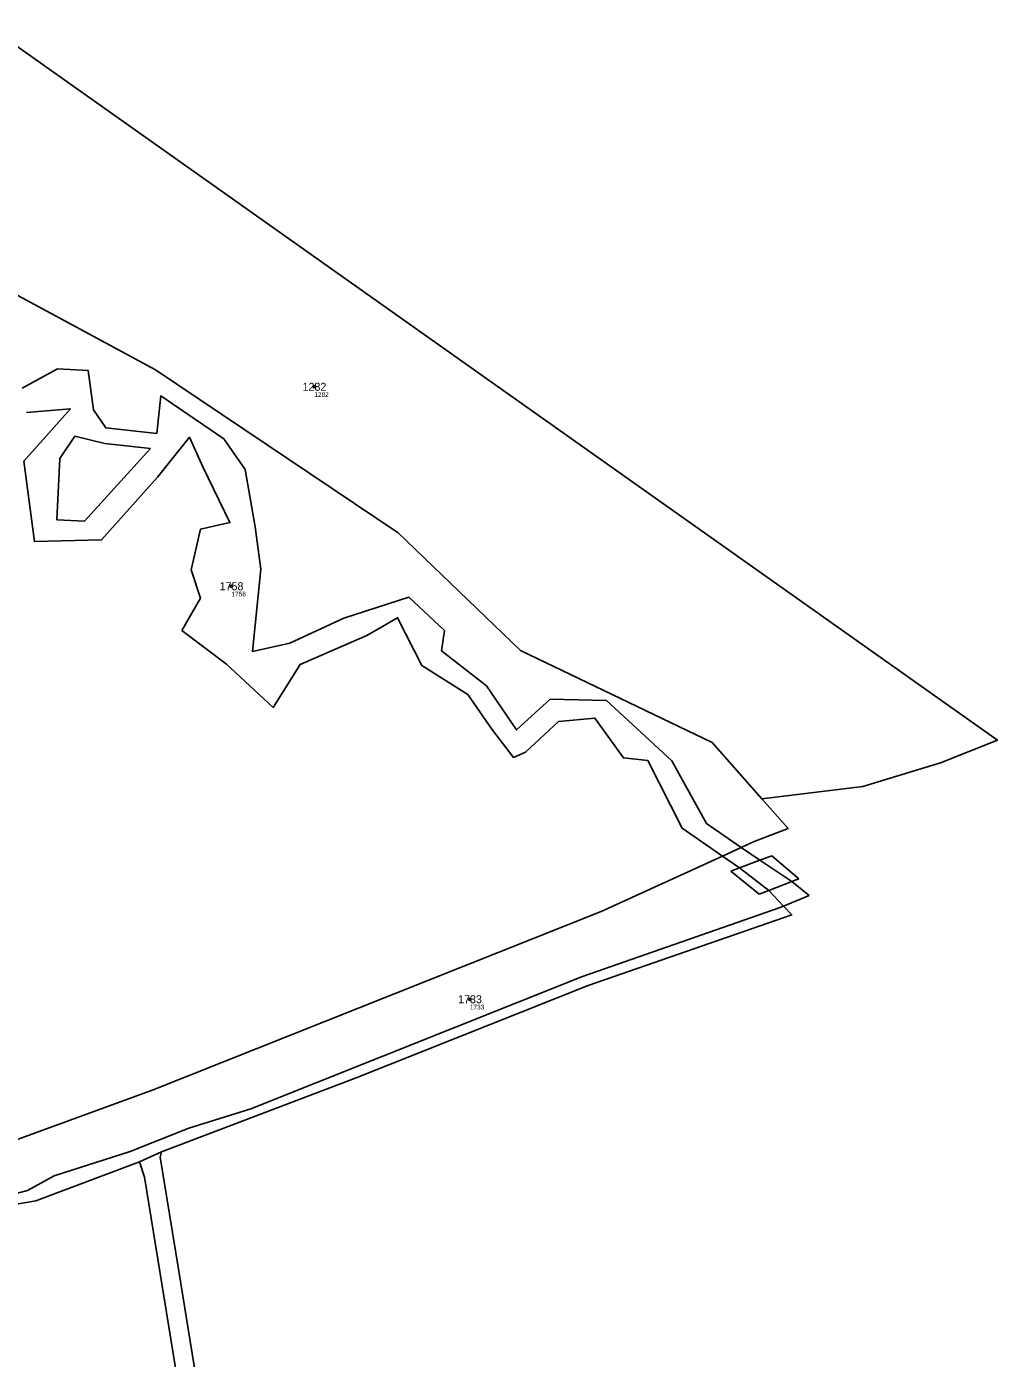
# Model space of a CAD drawing. Extents: x -781091 to -780384, y -1093010 to -1092030.
# Drawn here: x -780590.6 to -780384.4, y -1092590.4 to -1092307.5 of the extents above; entities that cross this region are included whole.
import ezdxf

# ---------------------------------------------------------------- set-up
doc = ezdxf.new("R2010")
doc.units = 0
for name, color, linetype in [('Vrstva 1', 7, 'Continuous'), ('Vrstva 2', 7, 'Continuous'), ('Vrstva 4', 7, 'Continuous'), ('Vrstva 50', 7, 'Continuous'), ('Vrstva 51', 7, 'Continuous')]:
    doc.layers.add(name, color=color, linetype=linetype)

msp = doc.modelspace()

# ---------------------------------------------------------------- linework, layer by layer
at = {"layer": 'Vrstva 1'}
for p, q in [((-780428.87, -1092477.84), (-780434.43, -1092471.52)), ((-780428.07, -1092496.18), (-780471.31, -1092511.15)), ((-780566.65, -1092548.58), (-780562, -1092546.47)), ((-780558.33, -1092571.84), (-780541.89, -1092672.78))]:
    msp.add_line(p, q, dxfattribs=at)
for points in [[(-780384.4, -1092459.05), (-780494.05, -1092381.46), (-780616.5, -1092294.82)], [(-780434.43, -1092471.52), (-780444.96, -1092459.56), (-780485.72, -1092440), (-780511.7, -1092415.04), (-780563.24, -1092380.4), (-780628.93, -1092345.03), (-780635.51, -1092325.46), (-780626.4, -1092311.9)], [(-780591.62, -1092384.31), (-780584.09, -1092380.2), (-780577.59, -1092380.54), (-780576.43, -1092388.86), (-780573.82, -1092392.75), (-780563, -1092393.9), (-780562.1, -1092385.91), (-780548.77, -1092395.06), (-780544.19, -1092401.58), (-780542.06, -1092413.74), (-780540.85, -1092422.73), (-780542.68, -1092440.2), (-780534.7, -1092438.42), (-780523.28, -1092433.14), (-780509.41, -1092428.65), (-780501.89, -1092435.79), (-780502.48, -1092440.08), (-780492.92, -1092447.52), (-780486.58, -1092456.87), (-780479.41, -1092450.33), (-780467.46, -1092450.64), (-780453.55, -1092463.43), (-780446.2, -1092476.76), (-780438.83, -1092481.84)], [(-780442.83, -1092483.67), (-780451.37, -1092477.74), (-780458.67, -1092463.36), (-780463.84, -1092462.82), (-780469.92, -1092454.36), (-780477.64, -1092455.07), (-780484.65, -1092461.6), (-780487.21, -1092462.7), (-780491.81, -1092456.74), (-780496.87, -1092449.32), (-780506.68, -1092443.21), (-780511.84, -1092433.06), (-780518.39, -1092436.81), (-780532.51, -1092442.95), (-780538.26, -1092452.08), (-780548.16, -1092442.92), (-780557.65, -1092435.73), (-780553.71, -1092428.88), (-780555.7, -1092422.88), (-780553.69, -1092414.22), (-780547.46, -1092412.85), (-780553.22, -1092400.98), (-780556.07, -1092394.72), (-780562.85, -1092403.17), (-780574.71, -1092416.51), (-780589, -1092416.87), (-780591.25, -1092399.82), (-780581.34, -1092388.68), (-780590.69, -1092389.44)], [(-780434.43, -1092471.52), (-780412.99, -1092468.92), (-780396.51, -1092463.88), (-780384.4, -1092459.05)], [(-780438.83, -1092481.84), (-780436.05, -1092480.57), (-780428.87, -1092477.84)], [(-780438.83, -1092481.84), (-780434.87, -1092484.57), (-780428.04, -1092489.08), (-780424.36, -1092492.02)], [(-780599.09, -1092546.21), (-780563.77, -1092533.33), (-780468.56, -1092495.42), (-780442.83, -1092483.67)], [(-780428.07, -1092496.18), (-780429.83, -1092494.3), (-780432.93, -1092490.97), (-780439.21, -1092486.18), (-780442.83, -1092483.67)], [(-780471.31, -1092511.15), (-780520.62, -1092530.74), (-780562, -1092546.47)], [(-780562, -1092546.47), (-780562.27, -1092547.65), (-780558.33, -1092571.84)], [(-780566.65, -1092548.58), (-780588.7, -1092556.87), (-780619.47, -1092562.21), (-780643.35, -1092566.12)], [(-780542.57, -1092690.03), (-780545.84, -1092673.37), (-780565.63, -1092551.86), (-780566.65, -1092548.58)]]:
    msp.add_lwpolyline(points, dxfattribs=at)
at = {"layer": 'Vrstva 4'}
for p, q in [((-780580.4, -1092394.52), (-780583.61, -1092399.24)), ((-780574.04, -1092396.04), (-780580.4, -1092394.52)), ((-780578.34, -1092412.57), (-780564.34, -1092397.11)), ((-780564.34, -1092397.11), (-780574.04, -1092396.04)), ((-780583.61, -1092399.24), (-780584.2, -1092412.26)), ((-780584.2, -1092412.26), (-780578.34, -1092412.57)), ((-780442.83, -1092483.67), (-780438.83, -1092481.84)), ((-780439.21, -1092486.18), (-780441.05, -1092486.86)), ((-780434.87, -1092484.57), (-780439.21, -1092486.18)), ((-780432.3, -1092483.62), (-780434.87, -1092484.57)), ((-780426.58, -1092488.51), (-780432.3, -1092483.62)), ((-780441.05, -1092486.86), (-780434.98, -1092491.76)), ((-780428.04, -1092489.08), (-780426.58, -1092488.51)), ((-780434.98, -1092491.76), (-780432.93, -1092490.97)), ((-780432.93, -1092490.97), (-780428.04, -1092489.08)), ((-780472.57, -1092509.26), (-780430.74, -1092494.68)), ((-780429.83, -1092494.3), (-780430.74, -1092494.68)), ((-780429.83, -1092494.3), (-780424.36, -1092492.02)), ((-780472.57, -1092509.26), (-780543, -1092537.37)), ((-780543, -1092537.37), (-780556.16, -1092541.48)), ((-780556.16, -1092541.48), (-780568.66, -1092546.39)), ((-780584.81, -1092551.57), (-780568.66, -1092546.39)), ((-780584.81, -1092551.57), (-780590.48, -1092554.71)), ((-780590.48, -1092554.71), (-780619.47, -1092562.21))]:
    msp.add_line(p, q, dxfattribs=at)
at = {"layer": 'Vrstva 50'}
for centre in [(-780529.52, -1092383.99994), (-780547.13, -1092426.35994), (-780496.47, -1092514.07994)]:
    msp.add_circle(centre, 0.25, dxfattribs=at)
at = {"layer": 'Vrstva 51'}
for points in [[(-780494.05, -1092381.46), (-780616.5, -1092294.82), (-780623.79, -1092305.99), (-780626.4, -1092311.9), (-780635.51, -1092325.46), (-780628.93, -1092345.03), (-780563.24, -1092380.4), (-780511.7, -1092415.04), (-780485.72, -1092440), (-780444.96, -1092459.56), (-780434.43, -1092471.52), (-780412.99, -1092468.92), (-780396.51, -1092463.88), (-780384.4, -1092459.05)], [(-780643.35, -1092566.12), (-780621.09, -1092702.81), (-780542.57, -1092690.03), (-780545.84, -1092673.37), (-780565.63, -1092551.86), (-780566.65, -1092548.58), (-780588.7, -1092556.87), (-780619.47, -1092562.21)]]:
    msp.add_lwpolyline(points, close=True, dxfattribs=at)
for points in [[(-780591.62, -1092384.31), (-780584.09, -1092380.2), (-780577.59, -1092380.54), (-780576.43, -1092388.86), (-780573.82, -1092392.75), (-780563, -1092393.9), (-780562.1, -1092385.91), (-780548.77, -1092395.06), (-780544.19, -1092401.58), (-780542.06, -1092413.74), (-780540.85, -1092422.73), (-780542.68, -1092440.2), (-780534.7, -1092438.42), (-780523.28, -1092433.14), (-780509.41, -1092428.65), (-780501.89, -1092435.79), (-780502.48, -1092440.08), (-780492.92, -1092447.52), (-780486.58, -1092456.87), (-780479.41, -1092450.33), (-780467.46, -1092450.64), (-780453.55, -1092463.43), (-780446.2, -1092476.76), (-780438.83, -1092481.84), (-780436.05, -1092480.57), (-780428.87, -1092477.84), (-780434.43, -1092471.52), (-780444.96, -1092459.56), (-780485.72, -1092440), (-780511.7, -1092415.04), (-780563.24, -1092380.4), (-780628.93, -1092345.03)], [(-780599.09, -1092546.21), (-780563.77, -1092533.33), (-780468.56, -1092495.42), (-780442.83, -1092483.67), (-780451.37, -1092477.74), (-780458.67, -1092463.36), (-780463.84, -1092462.82), (-780469.92, -1092454.36), (-780477.64, -1092455.07), (-780484.65, -1092461.6), (-780487.21, -1092462.7), (-780491.81, -1092456.74), (-780496.87, -1092449.32), (-780506.68, -1092443.21), (-780511.84, -1092433.06), (-780518.39, -1092436.81), (-780532.51, -1092442.95), (-780538.26, -1092452.08), (-780548.16, -1092442.92), (-780557.65, -1092435.73), (-780553.71, -1092428.88), (-780555.7, -1092422.88), (-780553.69, -1092414.22), (-780547.46, -1092412.85), (-780553.22, -1092400.98), (-780556.07, -1092394.72), (-780562.85, -1092403.17), (-780574.71, -1092416.51), (-780589, -1092416.87), (-780591.25, -1092399.82), (-780581.34, -1092388.68), (-780590.69, -1092389.44)], [(-780619.47, -1092562.21), (-780588.7, -1092556.87), (-780566.65, -1092548.58), (-780562, -1092546.47), (-780520.62, -1092530.74), (-780471.31, -1092511.15), (-780428.07, -1092496.18), (-780429.83, -1092494.3), (-780432.93, -1092490.97), (-780439.21, -1092486.18), (-780442.83, -1092483.67), (-780468.56, -1092495.42), (-780563.77, -1092533.33), (-780599.09, -1092546.21)]]:
    msp.add_lwpolyline(points, dxfattribs=at)

# ---------------------------------------------------------------- texts
at = {"layer": 'Vrstva 2'}
for s, p in [('1282', (-780532.027, -1092384.85)), ('1758', (-780549.637, -1092427.21)), ('1733', (-780498.977, -1092514.93))]:
    msp.add_text(s, height=1.699998, dxfattribs=at).set_placement(p)
at = {"layer": 'Vrstva 50'}
for s, p in [('1282', (-780529.52, -1092386.156)), ('1758', (-780547.13, -1092428.516)), ('1733', (-780496.47, -1092516.236))]:
    msp.add_text(s, height=0.999996, dxfattribs=at).set_placement(p)

doc.saveas('drawing.dxf')
